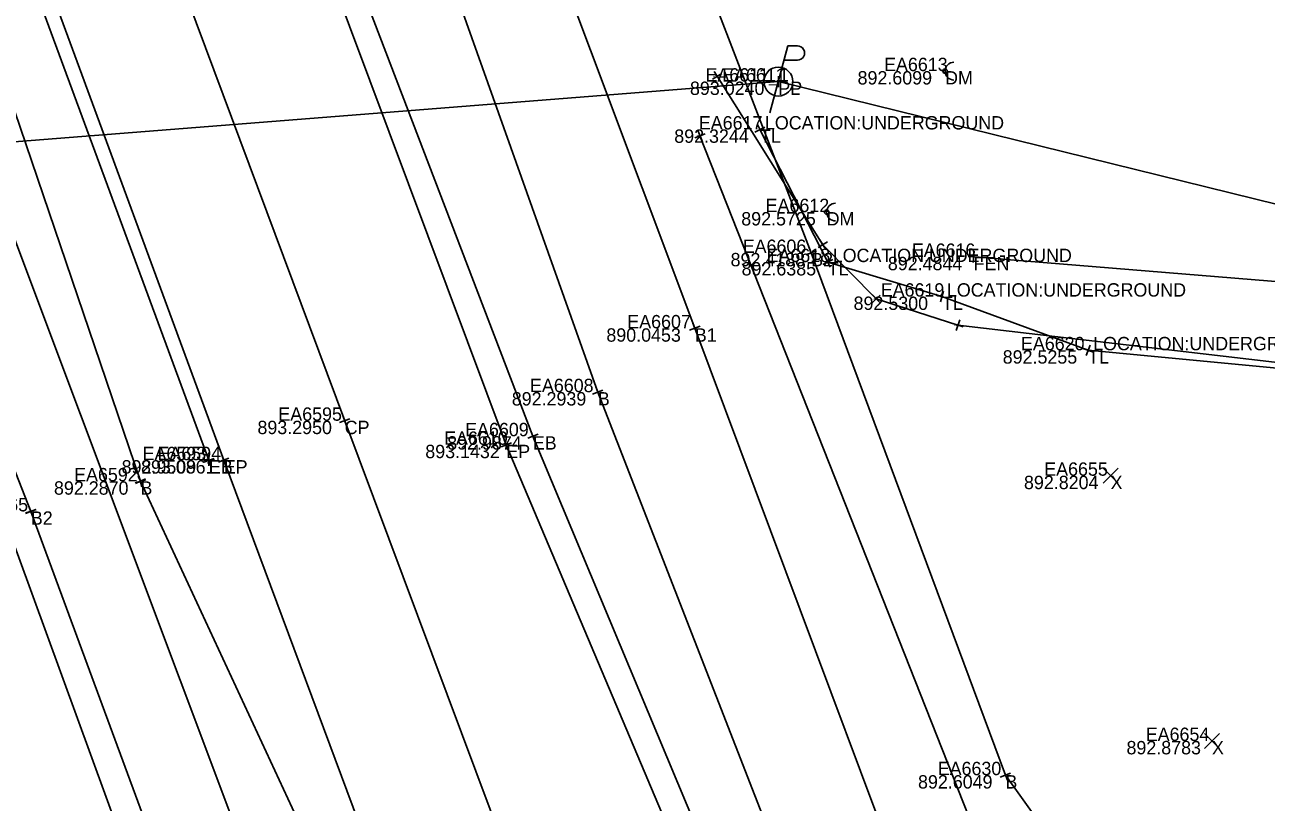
# Model space of a CAD drawing. Extents: x 179044 to 189691, y 286531 to 301257.
# Drawn here: x 180327.9 to 180439.4, y 300643.1 to 300712.9 of the extents above; entities that cross this region are included whole.
import ezdxf

# ---------------------------------------------------------------- set-up
doc = ezdxf.new("R2010")
doc.units = 0
for name, color, linetype in [('PV_X_COP', 7, 'Continuous'), ('PV_X_EOP', 7, 'Continuous'), ('PV_X_Shoulder_Aggregate', 7, 'Continuous'), ('RD_X_Fence', 7, 'Continuous'), ('SV_X_Break_Lines', 7, 'Continuous'), ('SV_X_Random_Point', 7, 'Continuous'), ('SV_X_Shot_Marker', 7, 'Continuous'), ('SV_X_Text_Comment', 7, 'Continuous'), ('SV_X_Text_Description', 7, 'Continuous'), ('SV_X_Text_Elevation', 7, 'Continuous'), ('SV_X_Text_Name', 7, 'Continuous'), ('SV_X_Toe_of_Slope', 7, 'Continuous'), ('SV_X_Top_of_Bank', 7, 'Continuous'), ('UT_X_Electric', 7, 'Continuous'), ('UT_X_Electric_Cells', 7, 'Continuous'), ('UT_X_Gas', 7, 'Continuous'), ('UT_X_Misc_Cells', 7, 'Continuous'), ('UT_X_Telecom', 7, 'Continuous')]:
    doc.layers.add(name, color=color, linetype=linetype)

msp = doc.modelspace()

# ---------------------------------------------------------------- linework, layer by layer
at = {"layer": 'PV_X_COP'}
msp.add_lwpolyline([(180435.29, 300467.37), (180412.88, 300528.12), (180394.43, 300576.01), (180387.7, 300594.07), (180373.61, 300631.85), (180356.6, 300677.34), (180322.12, 300769.7)], dxfattribs=at)
at = {"layer": 'PV_X_EOP'}
for points in [[(180336.02, 300768.96), (180371.12, 300675.18), (180391.48, 300627.03), (180401.14, 300618.13), (180409.94, 300612.3), (180420.83, 300608.19), (180437.01, 300607.02), (180453.78, 300606.87), (180491.75, 300607.1)], [(180345.73, 300673.8), (180312.19, 300764.8)], [(180395.24, 300541.25), (180387.76, 300561.4), (180375.37, 300595.1), (180360.49, 300634.17), (180345.73, 300673.8)]]:
    msp.add_lwpolyline(points, dxfattribs=at)
at = {"layer": 'PV_X_Shoulder_Aggregate'}
for points in [[(180337.75, 300769.37), (180373.5, 300675.95), (180393.39, 300628.4), (180402.34, 300620.16), (180411.15, 300613.97), (180421.2, 300610.61), (180436.88, 300608.74)], [(180344.4, 300673.8), (180311.06, 300764.05)]]:
    msp.add_lwpolyline(points, dxfattribs=at)
at = {"layer": 'RD_X_Fence'}
for points in [[(180399.73, 300496.44), (180388.78, 300528.13), (180377.77, 300557.4), (180364.67, 300592.43), (180350.69, 300630.43), (180323.97, 300701.53)], [(180413.11, 300692.06), (180502.15, 300684.78)]]:
    msp.add_lwpolyline(points, dxfattribs=at)
at = {"layer": 'SV_X_Break_Lines'}
for points in [[(180236.9, 300915.29), (180274.1, 300810.39), (180304.54, 300730.11), (180328.4, 300669.2)], [(180366.08, 300776.63), (180398.51, 300692.41)], [(180355.21, 300773.19), (180388.06, 300685.64), (180409.75, 300627.7)], [(180415.96, 300645.51), (180421.02, 300638.43), (180430.45, 300633.44), (180433.6, 300627.02), (180431.18, 300621.21), (180421.09, 300619.3), (180408.16, 300622.51), (180398.65, 300630.3), (180379.34, 300679.91), (180346.83, 300771.37)], [(180338.25, 300671.9), (180307.39, 300762.65)], [(180398.51, 300692.41), (180415.96, 300645.51)]]:
    msp.add_lwpolyline(points, dxfattribs=at)
at = {"layer": 'SV_X_Random_Point'}
for p, q in [((180424.75, 300671.73), (180426.08, 300673.07)), ((180424.75, 300673.07), (180426.08, 300671.73)), ((180433.85, 300647.91), (180435.19, 300649.25)), ((180433.85, 300649.25), (180435.19, 300647.91))]:
    msp.add_line(p, q, dxfattribs=at)
at = {"layer": 'SV_X_Shot_Marker'}
for p, q in [((180389.78, 300708.7), (180390.32, 300707.86)), ((180390.47, 300708.54), (180389.63, 300708.01)), ((180390.05, 300708.28), (180390.05, 300708.28)), ((180395.06, 300707.8), (180396.06, 300707.8)), ((180395.56, 300708.3), (180395.56, 300707.3)), ((180395.56, 300707.8), (180395.56, 300707.8)), ((180388.06, 300702.76), (180388.99, 300703.12)), ((180388.71, 300702.48), (180388.34, 300703.41)), ((180394.35, 300703.72), (180393.46, 300703.27)), ((180393.68, 300703.94), (180394.13, 300703.05)), ((180393.91, 300703.5), (180393.91, 300703.5)), ((180388.52, 300702.94), (180388.52, 300702.94)), ((180399.99, 300693.42), (180399.14, 300692.89)), ((180399.3, 300693.58), (180399.83, 300692.73)), ((180399.57, 300693.15), (180399.57, 300693.15)), ((180398.98, 300692.59), (180398.04, 300692.24)), ((180398.34, 300692.88), (180398.69, 300691.95)), ((180398.51, 300692.41), (180398.51, 300692.41)), ((180399.77, 300692.03), (180400.23, 300691.14)), ((180412.61, 300692.1), (180413.61, 300692.02)), ((180413.15, 300692.56), (180413.07, 300691.56)), ((180413.11, 300692.06), (180413.11, 300692.06)), ((180400.45, 300691.82), (180399.56, 300691.36)), ((180400, 300691.59), (180400, 300691.59)), ((180404.72, 300688.63), (180404, 300687.93)), ((180404.01, 300688.64), (180404.71, 300687.93)), ((180409.78, 300688.63), (180410.74, 300688.35)), ((180410.41, 300688.97), (180410.12, 300688.01)), ((180404.36, 300688.28), (180404.36, 300688.28)), ((180410.26, 300688.49), (180410.26, 300688.49)), ((180411.86, 300686.4), (180411.55, 300685.45)), ((180388.53, 300685.82), (180387.59, 300685.47)), ((180387.89, 300686.11), (180388.24, 300685.17)), ((180388.06, 300685.64), (180388.06, 300685.64)), ((180411.23, 300686.07), (180412.18, 300685.77)), ((180411.7, 300685.92), (180411.7, 300685.92)), ((180423.58, 300684.14), (180423.23, 300683.2)), ((180422.93, 300683.84), (180423.87, 300683.5)), ((180423.4, 300683.67), (180423.4, 300683.67)), ((180378.87, 300679.73), (180379.8, 300680.09)), ((180379.52, 300679.44), (180379.16, 300680.38)), ((180379.34, 300679.91), (180379.34, 300679.91)), ((180356.13, 300677.17), (180357.07, 300677.52)), ((180356.77, 300676.87), (180356.42, 300677.81)), ((180356.6, 300677.34), (180356.6, 300677.34)), ((180373.32, 300676.42), (180373.68, 300675.48)), ((180371.59, 300675.35), (180370.65, 300675)), ((180370.94, 300675.64), (180371.3, 300674.71)), ((180373.97, 300676.13), (180373.04, 300675.77)), ((180373.5, 300675.95), (180373.5, 300675.95)), ((180344.57, 300673.33), (180344.23, 300674.27)), ((180344.4, 300674.3), (180344.4, 300673.3)), ((180345.9, 300673.33), (180345.55, 300674.27)), ((180345.9, 300673.33), (180345.56, 300674.27)), ((180371.12, 300675.18), (180371.12, 300675.18)), ((180343.9, 300673.8), (180344.9, 300673.8)), ((180343.93, 300673.63), (180344.87, 300673.96)), ((180344.4, 300673.8), (180344.4, 300673.8)), ((180344.4, 300673.8), (180344.4, 300673.8)), ((180345.26, 300673.63), (180346.2, 300673.98)), ((180345.26, 300673.63), (180346.2, 300673.97)), ((180345.73, 300673.8), (180345.73, 300673.8)), ((180345.73, 300673.8), (180345.73, 300673.8)), ((180337.76, 300671.77), (180338.73, 300672.04)), ((180337.79, 300671.69), (180338.7, 300672.11)), ((180338.46, 300671.45), (180338.04, 300672.36)), ((180338.38, 300671.42), (180338.11, 300672.38)), ((180338.25, 300671.9), (180338.25, 300671.9)), ((180338.25, 300671.9), (180338.25, 300671.9)), ((180328.22, 300669.67), (180328.58, 300668.74)), ((180328.57, 300668.73), (180328.23, 300669.67)), ((180328.86, 300669.38), (180327.93, 300669.02)), ((180327.93, 300669.03), (180328.87, 300669.37)), ((180328.4, 300669.2), (180328.4, 300669.2)), ((180328.4, 300669.2), (180328.4, 300669.2)), ((180416.43, 300645.69), (180415.49, 300645.34)), ((180415.79, 300645.98), (180416.14, 300645.05)), ((180415.96, 300645.51), (180415.96, 300645.51))]:
    msp.add_line(p, q, dxfattribs=at)
at = {"layer": 'SV_X_Toe_of_Slope'}
for points in [[(180389.99, 300492.48), (180377.03, 300526.61), (180365.84, 300559.26), (180354.28, 300592.3), (180341.73, 300625.55), (180325.91, 300668.93)], [(180391.24, 300493.14), (180379.39, 300526.41), (180367.71, 300559.94), (180356.31, 300592.68), (180344.2, 300626.34), (180328.4, 300669.2)]]:
    msp.add_lwpolyline(points, dxfattribs=at)
at = {"layer": 'SV_X_Top_of_Bank'}
msp.add_lwpolyline([(180397.95, 300519.64), (180393.37, 300530.61), (180382.9, 300558.8), (180370.79, 300593.33), (180356.54, 300632.51), (180338.25, 300671.9)], dxfattribs=at)
at = {"layer": 'UT_X_Electric'}
msp.add_lwpolyline([(180111.81, 300685.43), (180395.56, 300707.8), (180463.97, 300690.94)], dxfattribs=at)
at = {"layer": 'UT_X_Electric_Cells'}
for p, q in [((180396.42, 300711), (180394.81, 300705)), ((180396.42, 300711), (180397.27, 300711)), ((180396.08, 300709.72), (180397.27, 300709.72))]:
    msp.add_line(p, q, dxfattribs=at)
msp.add_circle((180395.56, 300707.8), 1.3, dxfattribs=at)
msp.add_arc((180397.28, 300710.36), 0.638, 268.8767, 91.1233, dxfattribs=at)
at = {"layer": 'UT_X_Gas'}
msp.add_lwpolyline([(180490.47, 300448.38), (180476.39, 300497.95), (180471.56, 300513.1), (180457.1, 300544.93), (180444.55, 300576.64), (180429.4, 300607.12), (180413.67, 300639.28), (180388.52, 300702.94)], dxfattribs=at)
at = {"layer": 'UT_X_Misc_Cells'}
for centre in [(180410.54, 300708.74), (180399.9, 300696.08)]:
    msp.add_circle(centre, 0.2, dxfattribs=at)
for centre in [(180411.34, 300708.74), (180400.7, 300696.08)]:
    msp.add_arc(centre, 0.8, 90, 270, dxfattribs=at)
at = {"layer": 'UT_X_Telecom'}
for points in [[(180390.05, 300708.28), (180399.57, 300693.15), (180404.36, 300688.28), (180411.7, 300685.92), (180468.58, 300679.28), (180578.09, 300671.82), (180656.6, 300666.72), (180686.36, 300663.45), (180690.68, 300657.04), (180703.63, 300629.93), (180709.13, 300611.67), (180711.81, 300592.05), (180711.93, 300578.12), (180722.74, 300551.74)], [(180393.91, 300703.5), (180400, 300691.59), (180410.26, 300688.49), (180423.4, 300683.67), (180511.07, 300675.32)]]:
    msp.add_lwpolyline(points, dxfattribs=at)

# ---------------------------------------------------------------- texts
at = {"layer": 'SV_X_Text_Comment'}
for s, height, p in [('DM', 1.2, (180410.54, 300707.54)), ('TL', 0.06, (180390.05, 300708.22)), ('PP', 1.2, (180395.56, 300706.6)), ('PL', 1.2, (180395.56, 300706.6)), ('TL', 1.2, (180393.91, 300702.3)), ('GL', 0.06, (180388.52, 300702.88)), ('DM', 1.2, (180399.9, 300694.88)), ('TL', 0.06, (180399.57, 300693.09)), ('B2', 1.2, (180398.51, 300691.21)), ('FEN', 1.2, (180413.11, 300690.86)), ('TL', 1.2, (180400, 300690.39)), ('TL', 0.06, (180404.36, 300688.22)), ('TL', 1.2, (180410.26, 300687.29)), ('B1', 1.2, (180388.06, 300684.44)), ('TL', 0.06, (180411.7, 300685.86)), ('TL', 1.2, (180423.4, 300682.47)), ('B', 1.2, (180379.34, 300678.71)), ('CP', 1.2, (180356.6, 300676.14)), ('EB', 1.2, (180373.5, 300674.75)), ('EP', 1.2, (180371.12, 300673.98)), ('EB', 0.06, (180344.4, 300673.74)), ('EB', 1.2, (180344.4, 300672.6)), ('EP', 0.06, (180345.73, 300673.74)), ('EP', 1.2, (180345.73, 300672.6)), ('B', 0.06, (180338.25, 300671.84)), ('B', 1.2, (180338.25, 300670.7)), ('X', 1.2, (180425.41, 300671.2)), ('B', 0.06, (180328.4, 300669.14)), ('B2', 1.2, (180328.4, 300668)), ('X', 1.2, (180434.52, 300647.38)), ('B', 1.2, (180415.96, 300644.31))]:
    msp.add_text(s, height=height, dxfattribs=at).set_placement(p)
at = {"layer": 'SV_X_Text_Description'}
for p in [(180393.91, 300703.5), (180400, 300691.59), (180410.26, 300688.49), (180423.4, 300683.67)]:
    msp.add_text(' LOCATION:UNDERGROUND', height=1.2, dxfattribs=at).set_placement(p)
at = {"layer": 'SV_X_Text_Elevation'}
for s, height, p in [('892.6099', 1.2, (180402.68, 300707.54)), ('893.0240', 1.2, (180387.62, 300706.6)), ('893.0240', 1.2, (180387.62, 300706.6)), ('891.8440', 0.06, (180389.68, 300708.22)), ('892.3244', 1.2, (180386.21, 300702.3)), ('891.0640', 0.06, (180388.15, 300702.88)), ('892.5725', 1.2, (180392.23, 300694.88)), ('892.4760', 0.06, (180399.18, 300693.09)), ('892.4188', 1.2, (180391.27, 300691.21)), ('892.4844', 1.2, (180405.4, 300690.86)), ('892.6385', 1.2, (180392.26, 300690.39)), ('892.5300', 1.2, (180402.32, 300687.29)), ('892.5360', 0.06, (180403.97, 300688.22)), ('890.0453', 1.2, (180380.11, 300684.44)), ('892.5210', 0.06, (180411.34, 300685.86)), ('892.5255', 1.2, (180415.72, 300682.47)), ('892.2939', 1.2, (180371.61, 300678.71)), ('893.2950', 1.2, (180348.76, 300676.14)), ('892.9874', 1.2, (180365.81, 300674.75)), ('893.1432', 1.2, (180363.84, 300673.98)), ('892.9509', 1.2, (180336.56, 300672.6)), ('893.0861', 1.2, (180338.3, 300672.6)), ('892.9509', 0.06, (180344.01, 300673.74)), ('893.0861', 0.06, (180345.38, 300673.74)), ('892.2870', 1.2, (180330.48, 300670.7)), ('892.2870', 0.06, (180337.86, 300671.84)), ('892.8204', 1.2, (180417.63, 300671.2)), ('890.1528', 0.06, (180328.03, 300669.14)), ('892.8783', 1.2, (180426.84, 300647.38)), ('892.6049', 1.2, (180408.11, 300644.31))]:
    msp.add_text(s, height=height, dxfattribs=at).set_placement(p)
at = {"layer": 'SV_X_Text_Name'}
for s, height, p in [('EA6613', 1.2, (180405.06, 300708.74)), ('EA6611_1', 1.2, (180389.01, 300707.8)), ('EA6611', 1.2, (180390.51, 300707.8)), ('SV5044', 0.06, (180389.75, 300708.28)), ('EA6617', 1.2, (180388.42, 300703.5)), ('SV5043', 0.06, (180388.22, 300702.94)), ('EA6612', 1.2, (180394.42, 300696.08)), ('EA6606', 1.2, (180392.36, 300692.41)), ('SV5045', 0.06, (180399.26, 300693.15)), ('EA6616', 1.2, (180407.55, 300692.06)), ('EA6618', 1.2, (180394.5, 300691.59)), ('EA6619', 1.2, (180404.76, 300688.49)), ('SV5046', 0.06, (180404.05, 300688.28)), ('EA6607', 1.2, (180381.99, 300685.64)), ('SV5047', 0.06, (180411.4, 300685.92)), ('EA6620', 1.2, (180417.36, 300683.67)), ('EA6608', 1.2, (180373.25, 300679.91)), ('EA6595', 1.2, (180350.64, 300677.34)), ('EA6610', 1.2, (180365.53, 300675.18)), ('EA6609', 1.2, (180367.42, 300675.95)), ('EA6593', 1.2, (180338.44, 300673.8)), ('EA6594', 1.2, (180339.78, 300673.8)), ('EA6592', 1.2, (180332.29, 300671.9)), ('6593', 0.06, (180344.21, 300673.8)), ('6594', 0.06, (180345.54, 300673.8)), ('EA6655', 1.2, (180419.45, 300672.4)), ('6592', 0.06, (180338.06, 300671.9)), ('EA6565', 1.2, (180322.44, 300669.2)), ('6565', 0.06, (180328.21, 300669.2)), ('EA6654', 1.2, (180428.57, 300648.58)), ('EA6630', 1.2, (180409.88, 300645.51))]:
    msp.add_text(s, height=height, dxfattribs=at).set_placement(p)

doc.saveas('drawing.dxf')
